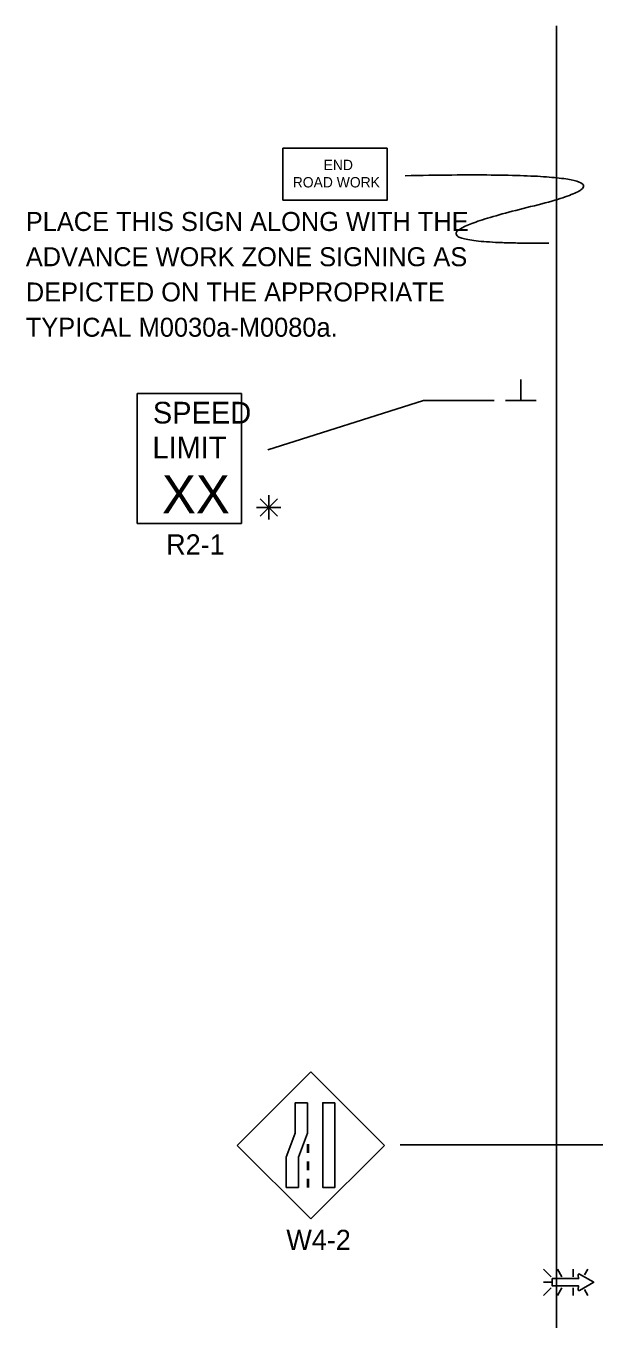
# Model space of a CAD drawing. Extents: x 16744 to 19504, y 5731 to 6974.
# Drawn here: x 17761.8 to 17971.4, y 6414.2 to 6891.2 of the extents above; entities that cross this region are included whole.
import ezdxf

# ---------------------------------------------------------------- set-up
doc = ezdxf.new("R2010")
doc.units = 0
for name, color, linetype in [('PAVT_EDGE_EX', 7, 'Continuous'), ('TRAFFIC_SIGNS_PR', 7, 'Continuous'), ('TYPICAL_TEXT_DIMEN_PR', 7, 'Continuous')]:
    doc.layers.add(name, color=color, linetype=linetype)

msp = doc.modelspace()

# ---------------------------------------------------------------- linework, layer by layer
at = {"layer": 'PAVT_EDGE_EX'}
msp.add_line((17957.5, 6891.16), (17957.5, 6061.98), dxfattribs=at)
at = {"layer": 'TRAFFIC_SIGNS_PR'}
for p, q in [((17802.87, 6755.64), (17841.27, 6755.64)), ((17802.87, 6707.64), (17802.87, 6755.64)), ((17841.27, 6707.64), (17841.27, 6755.64)), ((17802.87, 6707.64), (17841.27, 6707.64)), ((17866.91, 6505.46), (17839.76, 6478.31)), ((17894.06, 6478.31), (17866.91, 6505.46)), ((17839.76, 6478.31), (17866.91, 6451.15)), ((17865.66, 6478.8), (17865.66, 6475.6)), ((17866.06, 6478.8), (17866.06, 6475.6)), ((17866.91, 6451.15), (17894.06, 6478.31)), ((17865.66, 6472.4), (17865.66, 6469.2)), ((17866.06, 6472.4), (17866.06, 6469.2)), ((17865.66, 6466), (17865.66, 6462.8)), ((17866.06, 6466), (17866.06, 6462.8)), ((17955.52, 6429.83), (17952.7, 6432.65)), ((17957.82, 6432.65), (17959.45, 6429.83)), ((17963.61, 6429.83), (17963.61, 6432.65)), ((17969.08, 6432.65), (17967.87, 6430.56)), ((17955.52, 6427.8), (17952.7, 6427.8)), ((17955.52, 6425.77), (17952.7, 6422.94)), ((17959.47, 6425.77), (17957.84, 6422.94)), ((17963.61, 6425.77), (17963.61, 6422.94)), ((17967.79, 6425.13), (17969.05, 6422.94))]:
    msp.add_line(p, q, dxfattribs=at)
for points in [[(17856.62, 6826.82), (17895.02, 6826.82), (17895.02, 6846.02), (17856.62, 6846.02)], [(17865.66, 6494.04), (17865.66, 6482.86), (17862.32, 6473.98), (17862.32, 6462.8), (17857.82, 6462.8), (17857.82, 6473.98), (17861.17, 6482.86), (17861.17, 6494.04)], [(17875.8, 6494.04), (17875.8, 6462.8), (17871.31, 6462.8), (17871.31, 6494.04)]]:
    msp.add_lwpolyline(points, close=True, dxfattribs=at)
for points in [[(17965.43, 6430.48), (17965.66, 6429.18), (17955.94, 6429.18), (17955.94, 6426.44), (17965.66, 6426.44), (17965.43, 6425.14)], [(17965.93, 6424.78), (17971.24, 6427.8), (17965.93, 6430.84)]]:
    msp.add_lwpolyline(points, dxfattribs=at)
for centre, start, end in [((17965.77, 6430.54), 61.4833, 189.9593), ((17965.77, 6425.08), 170.7308, 298.8916)]:
    msp.add_arc(centre, 0.341, start, end, dxfattribs=at)
msp.add_open_spline([(17954.72, 6811.05), (17890.19, 6810.48), (18004.1, 6838.06), (17901.68, 6835.89)], degree=2, dxfattribs=at)
at = {"layer": 'TYPICAL_TEXT_DIMEN_PR'}
for p, q in [((17944.38, 6752.97), (17944.38, 6760.76)), ((17908.5, 6752.97), (17851.06, 6734.82)), ((17908.5, 6752.97), (17934.5, 6752.97)), ((17938.75, 6752.97), (17950, 6752.97)), ((17854.57, 6716.78), (17848.19, 6710.4)), ((17848.2, 6716.78), (17854.57, 6710.4)), ((17851.38, 6713.59), (17851.38, 6718.05)), ((17851.38, 6713.59), (17846.85, 6713.59)), ((17851.38, 6713.59), (17854.57, 6713.59)), ((17851.38, 6713.59), (17855.86, 6713.59)), ((17851.38, 6713.59), (17851.38, 6709.09)), ((17899.85, 6478.44), (17977.7, 6478.44))]:
    msp.add_line(p, q, dxfattribs=at)

# ---------------------------------------------------------------- texts
at = {"layer": 'TRAFFIC_SIGNS_PR'}
for s, height, p in [('END', 3.831, (17871.62, 6837.95)), ('ROAD WORK', 3.831, (17860.23, 6831.57)), ('PLACE THIS SIGN ALONG WITH THE', 7, (17761.79, 6815.52)), ('ADVANCE WORK ZONE SIGNING AS', 7, (17761.79, 6802.52)), ('DEPICTED ON THE APPROPRIATE', 7, (17761.79, 6789.52)), ('TYPICAL M0030a-M0080a.', 7, (17761.79, 6776.52)), ('SPEED', 8, (17808.64, 6744.51)), ('LIMIT', 8, (17808.48, 6731.7)), ('XX', 14.031, (17811.99, 6711.4)), ('R2-1', 7.44, (17813.55, 6696.2)), ('W4-2', 7.44, (17857.87, 6439.72))]:
    msp.add_text(s, height=height, dxfattribs=at).set_placement(p)

doc.saveas('drawing.dxf')
